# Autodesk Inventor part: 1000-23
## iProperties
Created: 2007-03
Part Number: 1000-23
Document SubType Name: Modeling
Designer: Andy Moles
Material: Rubber
Mass: 0.111229 g
Surface Area: 4.22116 cm^2
Volume: 0.119601 cm^3
Density: 0.93 g/cm^3
Author: Andy Moles
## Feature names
1. Base1
